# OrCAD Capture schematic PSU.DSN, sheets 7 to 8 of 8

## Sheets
7 FPGA: size A3; title: CONTINUOUS POWER SUPPLY ADC ACQUISITION MODE; note: POF_TMR
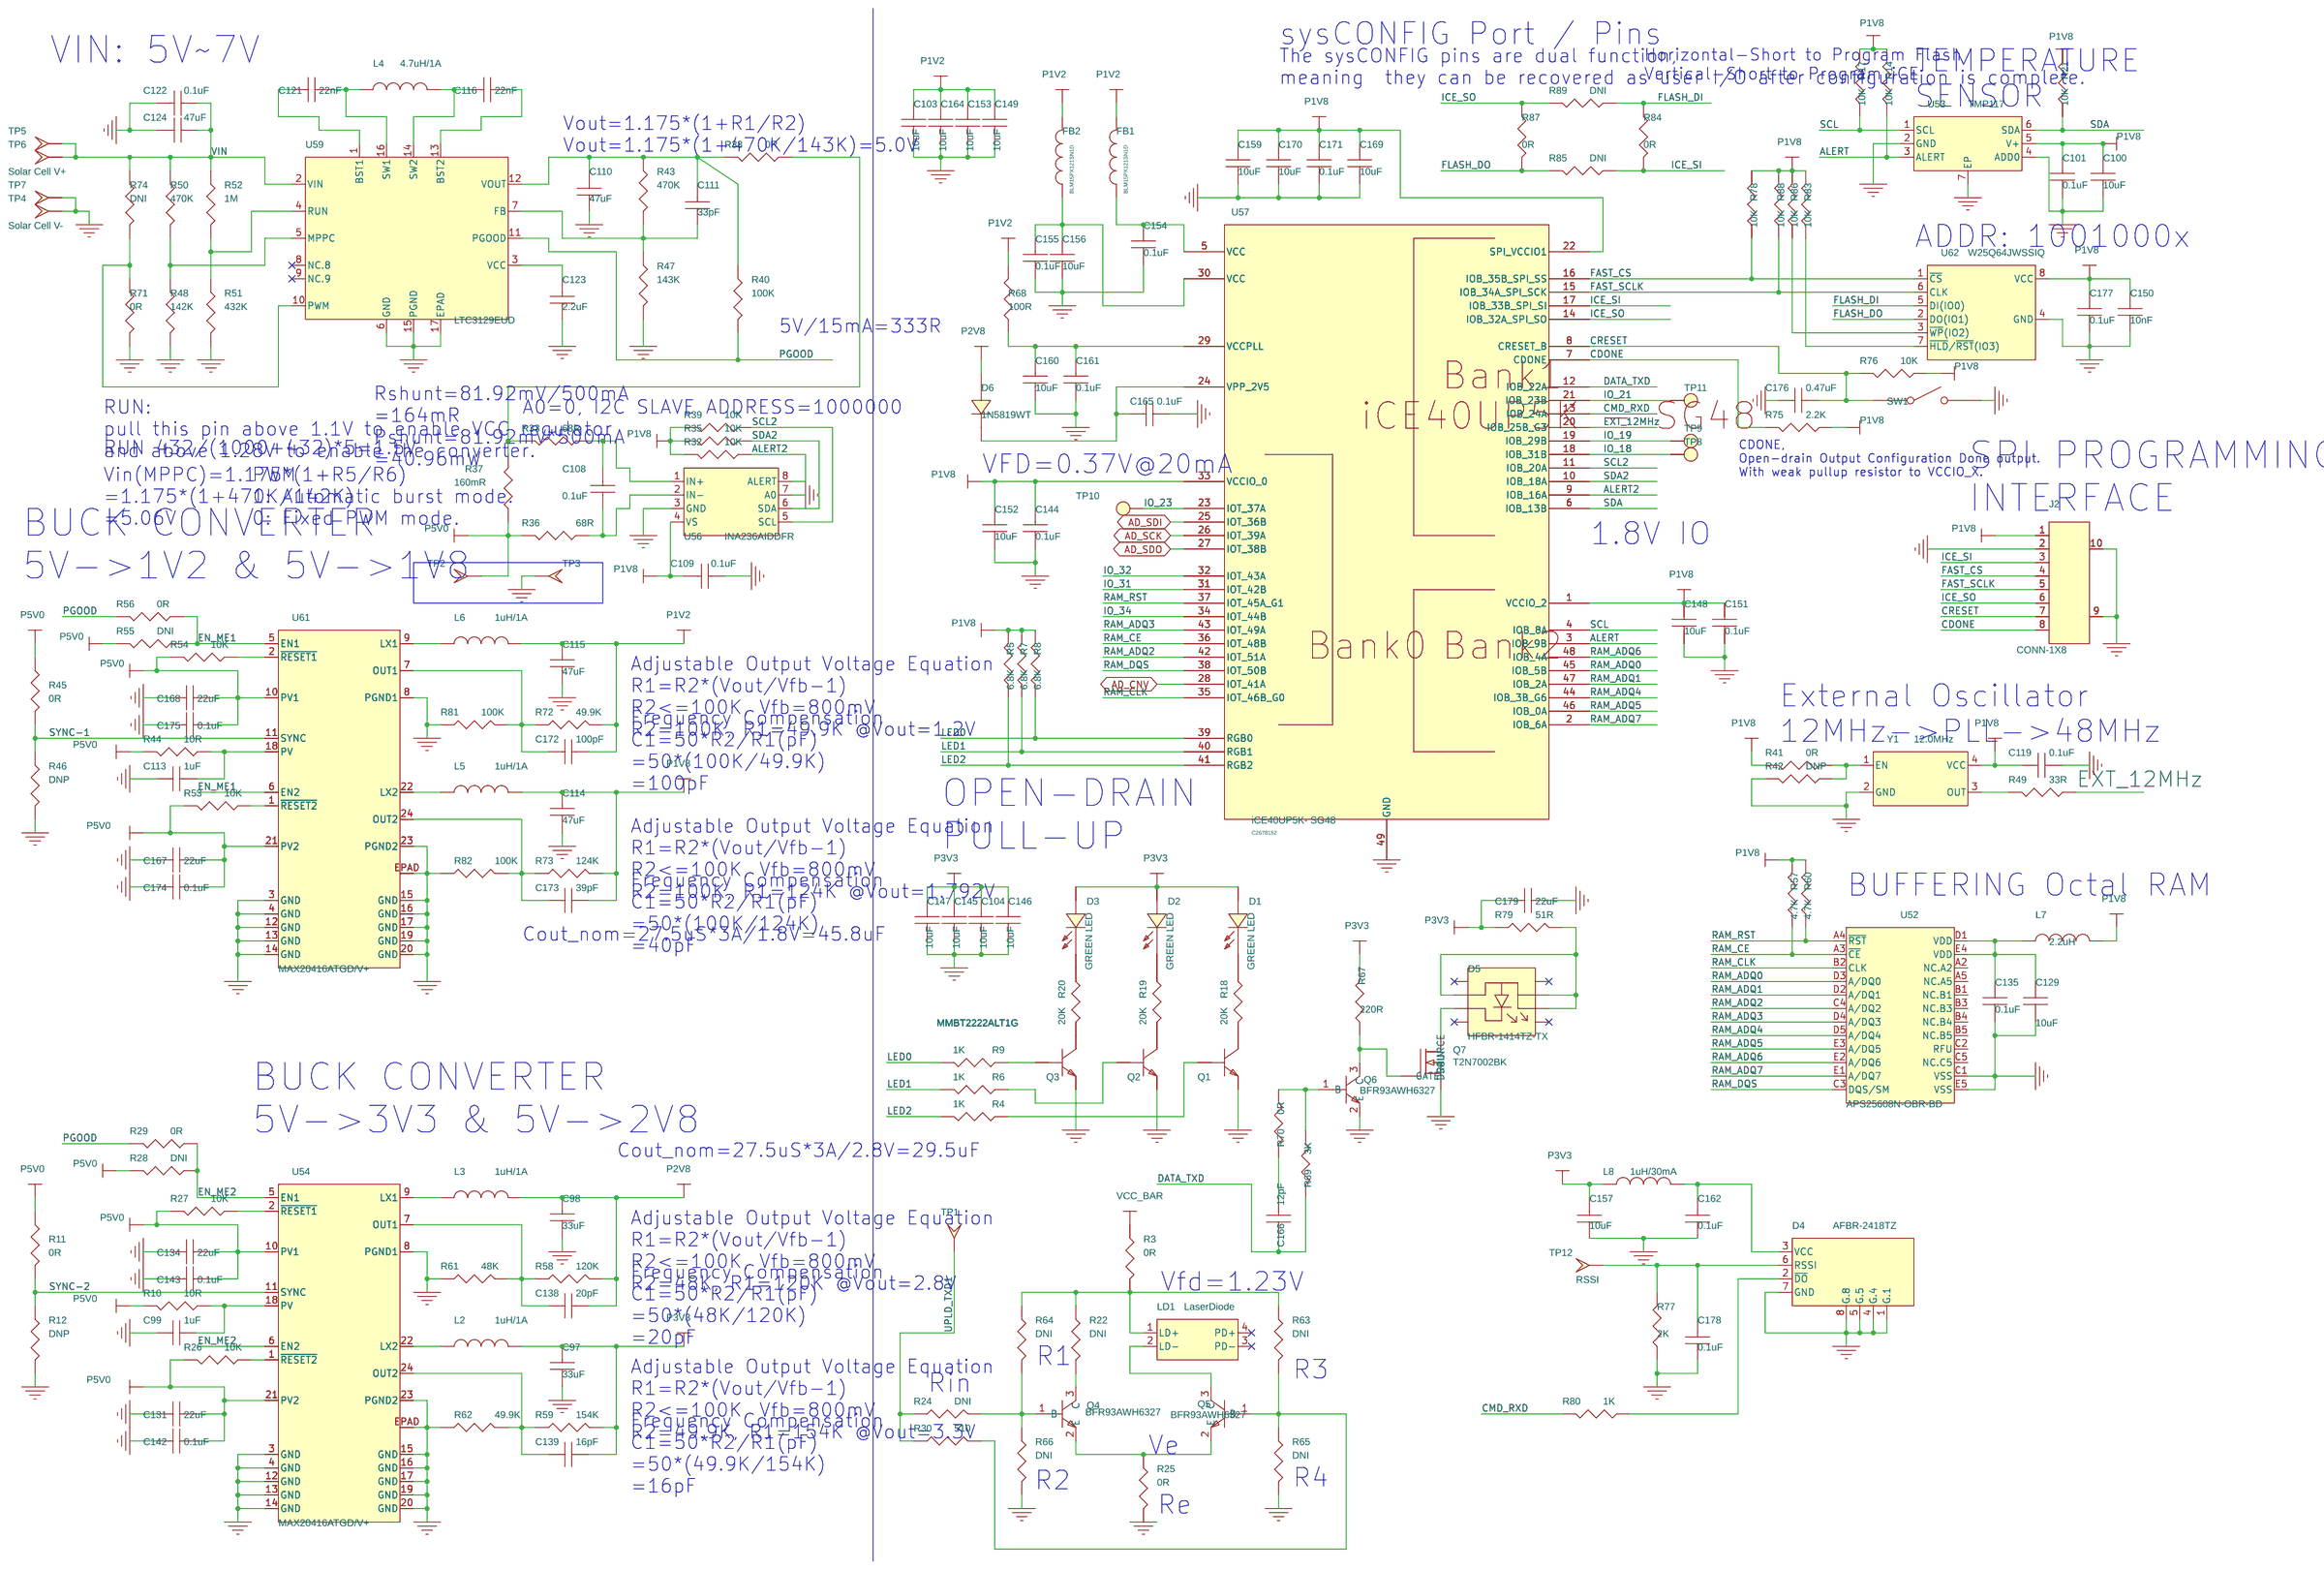
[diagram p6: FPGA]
8 BLOCK: title: PART ONE - POWER SUPPLY UNIT BLOCK DIAGRAM; note: PoF TINY DUAL CAMERA PROJECT
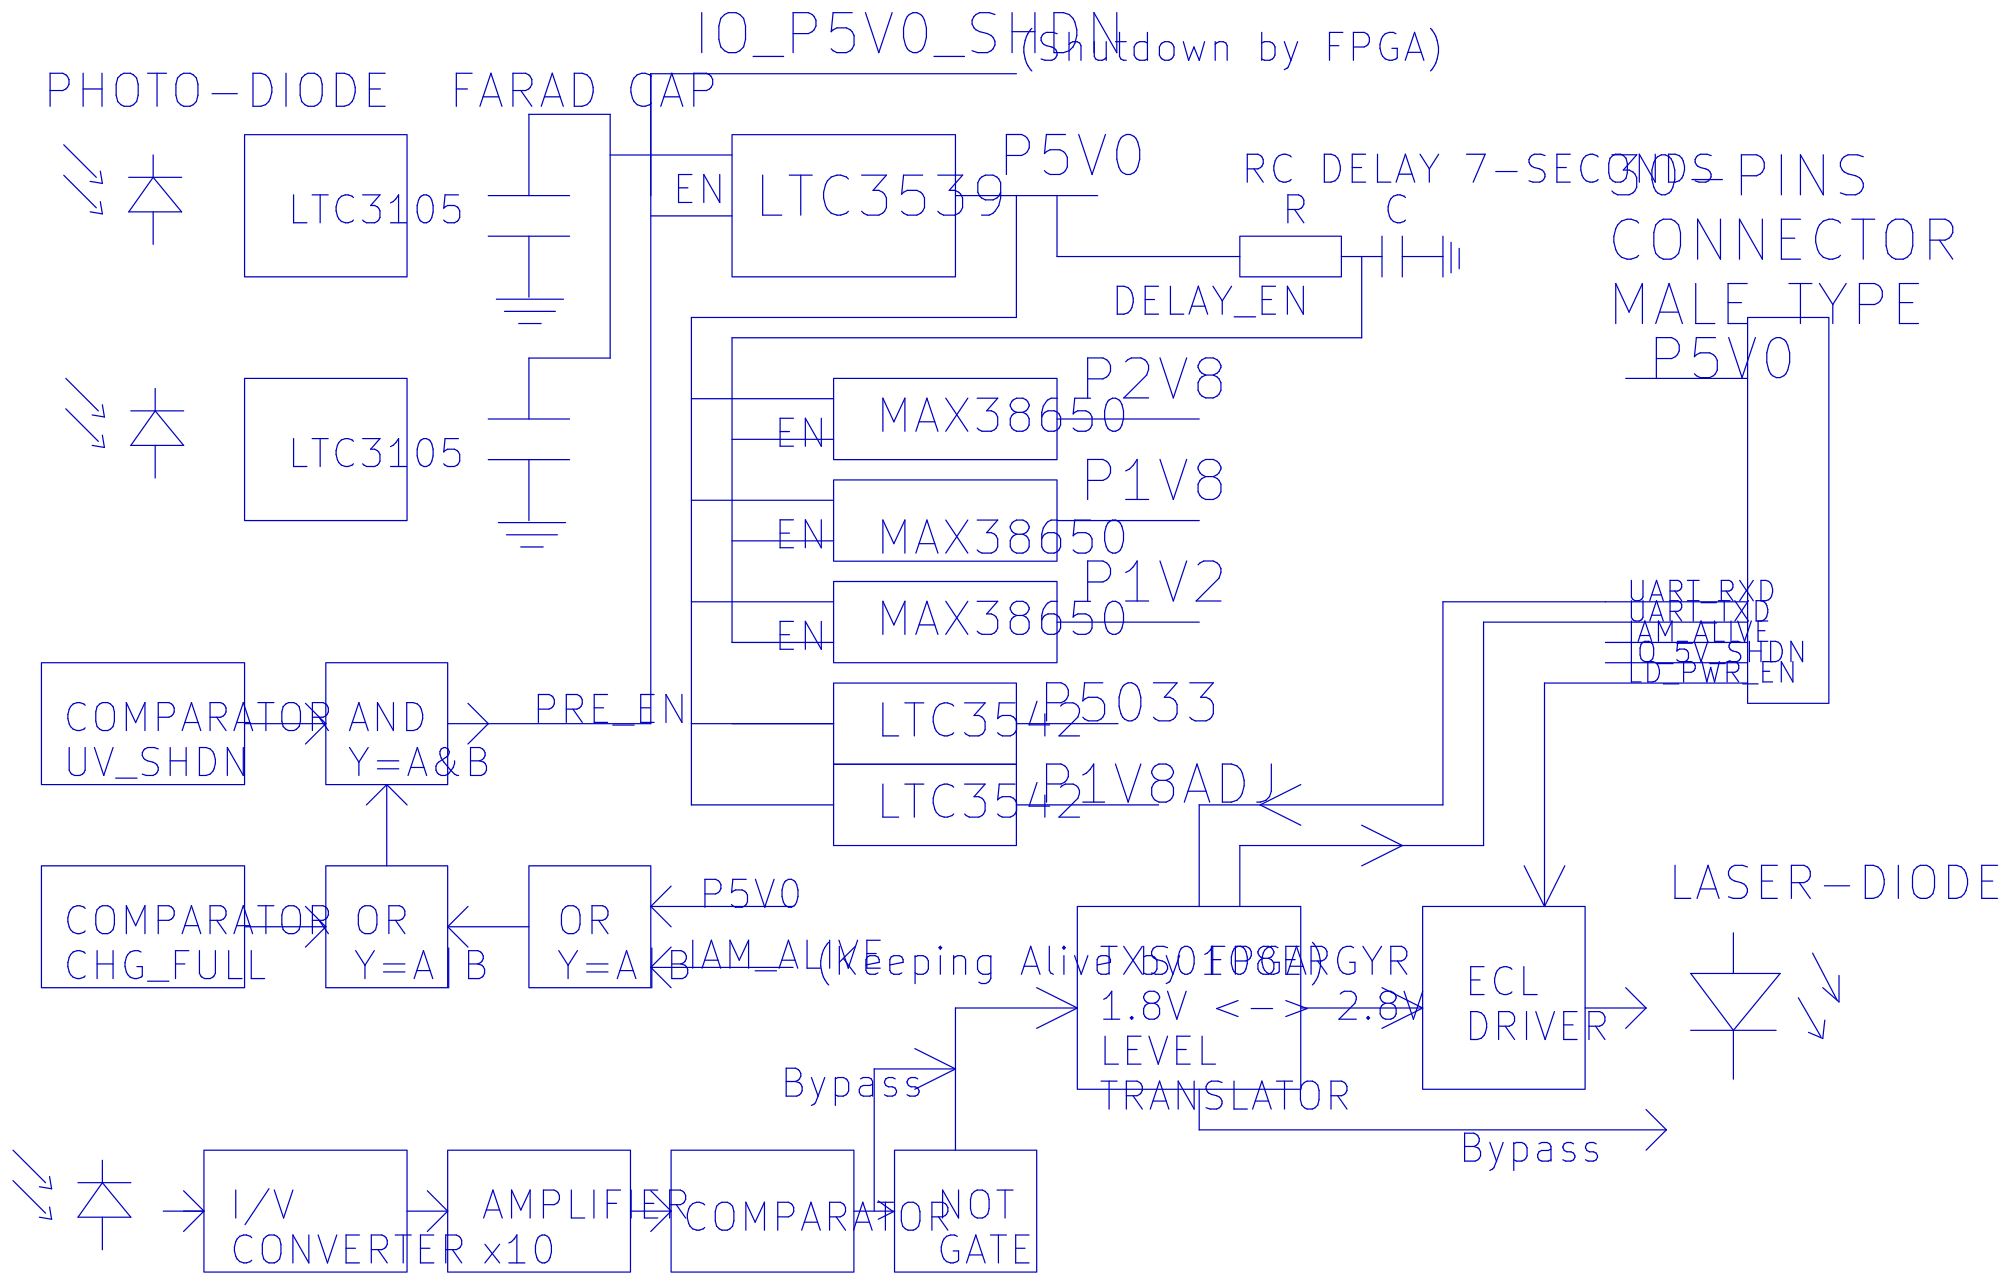
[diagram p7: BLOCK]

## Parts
C97  33uF  [C1206_SMT]
C98  33uF  [C1206_SMT]
C99  1uF  [C0402_SMT]
C100  10uF  [C0402_SMT]
C101  0.1uF  [C0402_SMT]
C103  10uF  [C0402_SMT]
C104  10uF  [C0402_SMT]
C108  0.1uF  [C0402_SMT]
C109  0.1uF  [C0402_SMT]
C110  47uF  [C1206_SMT]
C111  33pF  [C0402_SMT]
C113  1uF  [C0402_SMT]
C114  47uF  [C1206_SMT]
C115  47uF  [C1206_SMT]
C116  22nF  [C0402_SMT]
C119  0.1uF  [C0402_SMT]
C121  22nF  [C0402_SMT]
C122  0.1uF  [C0402_SMT]
C123  2.2uF  [C0402_SMT]
C124  47uF  [C1206_SMT]
C129  10uF  [C0603_SMT]
C131  22uF  [C0603_SMT]
C134  22uF  [C0603_SMT]
C135  0.1uF  [C0402_SMT]
C138  20pF  [C0402_SMT]
C139  16pF  [C0402_SMT]
C142  0.1uF  [C0402_SMT]
C143  0.1uF  [C0402_SMT]
C144  0.1uF  [C0402_SMT]
C145  10uF  [C0402_SMT]
C146  10uF  [C0402_SMT]
C147  10uF  [C0402_SMT]
C148  10uF  [C0402_SMT]
C149  10uF  [C0402_SMT]
C150  10nF  [C0402_SMT]
C151  0.1uF  [C0402_SMT]
C152  10uF  [C0402_SMT]
C153  10uF  [C0402_SMT]
C154  0.1uF  [C0402_SMT]
C155  0.1uF  [C0402_SMT]
C156  10uF  [C0402_SMT]
C157  10uF  [C0402_SMT]
C159  10uF  [C0402_SMT]
C160  10uF  [C0402_SMT]
C161  0.1uF  [C0402_SMT]
C162  0.1uF  [C0402_SMT]
C164  10uF  [C0402_SMT]
C165  0.1uF  [C0402_SMT]
C166  12pF  [C0402_SMT]
C167  22uF  [C0603_SMT]
C168  22uF  [C0603_SMT]
C169  10uF  [C0402_SMT]
C170  10uF  [C0402_SMT]
C171  0.1uF  [C0402_SMT]
C172  100pF  [C0402_SMT]
C173  39pF  [C0402_SMT]
C174  0.1uF  [C0402_SMT]
C175  0.1uF  [C0402_SMT]
C176  0.47uF  [C0402_SMT]
C177  0.1uF  [C0402_SMT]
C178  0.1uF  [C0402_SMT]
C179  22uF  [C0603_SMT]
D1  GREEN LED  [LED0402_SMT]
D2  GREEN LED  [LED0402_SMT]
D3  GREEN LED  [LED0402_SMT]
D4  AFBR-2418TZ  [AFBR-2418TZ]
D5  HFBR-1414TZ-TX  [HFBR-1414TZ-TX]
D6  1N5819WT  [SOD-523]
FB1  BLM15PX121SN1D  [L0402_SMT]
FB2  BLM15PX121SN1D  [L0402_SMT]
J2  CONN-1X8  [FPC-0D5-8P]
L2  1uH/1A  [L1210]
L3  1uH/1A  [L1210]
L4  4.7uH/1A  [IND_SMD_4D4X4D2]
L5  1uH/1A  [L1210]
L6  1uH/1A  [L1210]
L7  2.2uH  [L0402]
L8  1uH/30mA  [L0402_SMT]
LD1  LaserDiode  [LD_CIR_THR_4P]
Q1  MMBT2222ALT1G  [SOT-23-3]
Q2  MMBT2222ALT1G  [SOT-23-3]
Q3  MMBT2222ALT1G  [SOT-23-3]
Q4  BFR93AWH6327  [SOT23-3]
Q5  BFR93AWH6327  [SOT23-3]
Q6  BFR93AWH6327  [SOT23-3]
Q7  T2N7002BK  [SOT23-3]
R3  0R  [R0402_SMT]
R4  1K  [R0402_SMT]
R5  6.8K  [R0402_SMT]
R6  1K  [R0402_SMT]
R7  6.8K  [R0402_SMT]
R8  6.8K  [R0402_SMT]
R9  1K  [R0402_SMT]
R10  10R  [R0402_SMT]
R11  0R  [R0402_SMT]
R12  DNP  [R0402_SMT]
R14  10K  [R0402_SMT]
R17  10K  [R0402_SMT]
R18  20K  [R0402_SMT]
R19  20K  [R0402_SMT]
R20  20K  [R0402_SMT]
R21  10K  [R0402_SMT]
R22  DNI  [R0402_SMT]
R24  DNI  [R0402_SMT]
R25  0R  [R0402_SMT]
R26  10K  [R0402_SMT]
R27  10K  [R0402_SMT]
R28  DNI  [R0402_SMT]
R29  0R  [R0402_SMT]
R30  510  [R0402_SMT]
R32  10K  [R0402_SMT]
R33  68R  [R0402_SMT]
R35  10K  [R0402_SMT]
R36  68R  [R0402_SMT]
R37  160mR  [R0805_SMT]
R38  0R  [R0402_SMT]
R39  10K  [R0402_SMT]
R40  100K  [R0402_SMT]
R41  0R  [R0402_SMT]
R42  DNP  [R0402_SMT]
R43  470K  [R0402_SMT]
R44  10R  [R0402_SMT]
R45  0R  [R0402_SMT]
R46  DNP  [R0402_SMT]
R47  143K  [R0402_SMT]
R48  142K  [R0402_SMT]
R49  33R  [R0402_SMT]
R50  470K  [R0402_SMT]
R51  432K  [R0402_SMT]
R52  1M  [R0402_SMT]
R53  10K  [R0402_SMT]
R54  10K  [R0402_SMT]
R55  DNI  [R0402_SMT]
R56  0R  [R0402_SMT]
R57  4.7K  [R0402_SMT]
R58  120K  [R0402_SMT]
R59  154K  [R0402_SMT]
R60  4.7K  [R0402_SMT]
R61  48K  [R0402_SMT]
R62  49.9K  [R0402_SMT]
R63  DNI  [R0402_SMT]
R64  DNI  [R0402_SMT]
R65  DNI  [R0402_SMT]
R66  DNI  [R0402_SMT]
R67  220R  [R0402_SMT]
R68  100R  [R0402_SMT]
R69  3K  [R0402_SMT]
R70  0R  [R0402_SMT]
R71  0R  [R0402_SMT]
R72  49.9K  [R0402_SMT]
R73  124K  [R0402_SMT]
R74  DNI  [R0402_SMT]
R75  2.2K  [R0402_SMT]
R76  10K  [R0402_SMT]
R77  2K  [R0402_SMT]
R78  10K  [R0402_SMT]
R79  51R  [R0402_SMT]
R80  1K  [R0402_SMT]
R81  100K  [R0402_SMT]
R82  100K  [R0402_SMT]
R83  10K  [R0402_SMT]
R84  0R  [R0402_SMT]
R85  DNI  [R0402_SMT]
R86  10K  [R0402_SMT]
R87  0R  [R0402_SMT]
R88  10K  [R0402_SMT]
R89  DNI  [R0402_SMT]
SW1  SW KEY-SPST  [SW_SMD_2P_L3D9_W3D0_P4D5]
TP1  1  [TP_THR_1D0_1D5]
TP2  Solar Cell V+  [TP_THR_REC_1D5_3D5]
TP3  Solar Cell V+  [TP_THR_REC_1D5_3D5]
TP4  Solar Cell V-  [TP_THR_1D8_1D2]
TP5  Solar Cell V+  [TP_THR_1D8_1D2]
TP6  Solar Cell V+  [TP_THR_1D8_1D2]
TP7  Solar Cell V-  [TP_THR_1D8_1D2]
TP8  T POINT R  [TP_SMD_1D0_NP]
TP9  T POINT R  [TP_SMD_1D0_NP]
TP10  T POINT R  [TP_SMD_1D0_NP]
TP11  T POINT R  [TP_SMD_1D0_NP]
TP12  RSSI  [TP_THR_1D8_1D2]
U52  APS25608N-OBR-BD  [BGA-24]
U53  TMP117  [WDFN-6-EP-2x2]
U54  MAX20416ATGD/V+  [TQFN-24]
U56  INA236AIDDFR  [SOT-23-8]
U57  iCE40UP5K- SG48  [QFN-48]
U59  LTC3129EUD  [QFN-16-3x3]
U61  MAX20416ATGD/V+  [TQFN-24]
U62  W25Q64JWSSIQ  [SOIC-8]
Y1  12.0MHz  [SMD2520-4P]

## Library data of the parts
C97 C98 C110 C114 C115 C124 = CAP_NP: Memo: TDK MLCC 10V CGA5L1X7S1A226MT0Y0N; SIGNAL_MODEL: DEFAULT_CAPACITOR_2.2e+07pF_2_1
C99 C111 C113 C116 C121 C123 C131 C134 C142 C143 C157 C162 C167 C168 C174 C175 C178 C179 = CAP_NP: Memo: MLCC 10V - Kyocera AVXF951A106MPAAQ2; SIGNAL_MODEL: DEFAULT_CAPACITOR_1e+07pF_2_1
C100 C101 = CAP_NP
C103 C104 C145-C149 C152 C153 C156 C159 C160 C164 C169 C170 = CAP_NP: JLC: C15195
C108 C109 C122 = CAP_NP: JLC: C327064; SIGNAL_MODEL: DEFAULT_CAPACITOR_33.000000pF_2_1
C119 C138 C139 C166 C172 C173 = CAP_NP: JLC: C307331; Memo: MLCC 10V - Kyocera AVXF951A106MPAAQ2; SIGNAL_MODEL: DEFAULT_CAPACITOR_1e+07pF_2_1
C129 = CAP_NP: JLC: C96446
C135 C144 C151 C154 C161 C165 C176 C177 = CAP_NP: JLC: C307331
C150 C155 C171 = CAP_NP: JLC: C14445
D1-D3 = LED: JLC: C130723
D4 = AFBR-2418TZ
D5 = HFBR-1414TZ-TX
D6 = DIODE: JLC: C83482
FB1 FB2 = INDUCTOR: JLC: C14709
J2 = CONN-1X8
L2-L7 = INDUCTOR: JLC: C167208; Memo: 4.7uH 1A - TDK VLS3015ET-4R7M 3.0mm(L)*3.0mm(W)*1.5mm(H); SIGNAL_MODEL: DEFAULT_INDUCTOR_4700nH_2_1
L8 = INDUCTOR
LD1 = LaserDiode_0: Memo: Laser Diode
Q1-Q3 = MMBT2222AL: JLC: C82460
Q4-Q6 = 2SC1815: JLC: C727146; Memo: NPN TRANSISTOR
Q7 = MOSFET_N_0
R3 R22 R25 R67 R77 R79 R80 = R: SIGNAL_MODEL: DEFAULT_RESISTOR_40.000000OHM_2_1
R4 R6 R9 R69 R70 R76 R78 R83-R89 = R: JLC: C60490
R5 R7 R8 R14 R17-R21 = R: JLC: C2930116
R10-R12 R26-R29 R38 R40-R56 R58 R59 R61 R62 R71-R74 R81 R82 = R: JLC: C106231; SIGNAL_MODEL: DEFAULT_RESISTOR_10000OHM_2_1
R24 R30 R63-R66 = R: SIGNAL_MODEL: DEFAULT_RESISTOR_510.000000OHM_2_1
R32 R33 R35-R37 R39 = R
R57 R60 = R: JLC: C105871
R68 = R: JLC: C106232
R75 = R: JLC: C114762
SW1 = SW_KEY-SPST: JLC: C720477
TP1-TP7 TP12 = T_POINT_A: Memo: SMD Test Point Outer Diameter 2.0mm
TP8-TP11 = T_POINT_R
U52 = APS25608N-OBR-BD_2: JLC: Mouser
U53 = TMP117
U54 U61 = MAX20416ATGD_V+
U56 = INA236AIDDFR_v2
U57 = iCE40UP5K-_SG48: JLC: C2678152
U59 = LTC3129EUD
U62 = W25Q64JW: JLC: C2985658
Y1 = OSCILLATOR

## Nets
GND: C97.2 C98.2 C99.1 C100.2 C101.2 C103.2 C104.2 C109.1 C110.1 C113.1 C114.2 C115.2 C119.2 C122.2 C123.1 C124.2 C129.2 C131.1 C134.1 C135.2 C142.1 C143.1 C144.2 C145.2 C146.2 C147.2 C148.2 C149.2 C150.2 C151.2 C152.2 C153.2 C154.2 C155.2 C156.2 C157.1 C159.2 C160.2 C161.2 C162.1 C164.2 C165.2 C167.1 C168.1 C169.2 C170.2 C171.2 C174.1 C175.1 C176.1 C177.2 C178.1 C179.2 D4.1(G.1) D4.4(G.4) D4.5(G.5) D4.7(GND) D4.8(G.8) J2.2 J2.9 J2.10 Q1.2(EMITTER) Q2.2(EMITTER) Q3.2(EMITTER) Q6.2(E) Q7.2(SOURCE) R12.2 R25.2 R42.2 R46.2 R47.2 R48.2 R51.2 R61.1 R62.1 R65.2 R66.2 R71.2 R77.1 R81.1 R82.1 SW1.2 TP3.1(TP) TP4.1(TP) TP7.1(TP) U52.C1(VSS) U52.E5(VSS) U53.2(GND) U53.4(ADD0) U53.7(EP) U54.3(GND) U54.4(GND) U54.8(PGND1) U54.12(GND) U54.13(GND) U54.14(GND) U54.15(GND) U54.16(GND) U54.17(GND) U54.19(GND) U54.20(GND) U54.23(PGND2) U54.EPAD U56.3(GND) U56.7(A0) U57.49(GND) U59.6(GND) U59.15(PGND) U59.17(EPAD) U61.3(GND) U61.4(GND) U61.8(PGND1) U61.12(GND) U61.13(GND) U61.14(GND) U61.15(GND) U61.16(GND) U61.17(GND) U61.19(GND) U61.20(GND) U61.23(PGND2) U61.EPAD U62.4(GND) Y1.2(GND) ; also on sheet 2 6
P1V2: C103.1 C115.1 C149.1 C153.1 C164.1 C172.2 FB1.2 FB2.2 L6.2 R68.2 R72.2
P1V8: C100.1 C101.1 C109.2 C114.1 C119.1 C144.1 C148.1 C150.1 C151.1 C152.1 C159.1 C169.1 C170.1 C171.1 C173.2 C177.1 J2.1 L5.2 L7.2 R5.2 R7.2 R8.2 R14.2 R17.2 R21.2 R32.2 R35.2 R39.2 R41.2 R57.2 R60.2 R73.2 R75.1 R76.1 R78.2 R83.2 R86.2 R88.2 U53.5(V+) U56.4(VS) U57.1(VCCIO_2) U57.22(SPI_VCCIO1) U57.33(VCCIO_0) U62.8(VCC) Y1.4(VCC) ; also on sheet 2 6
P2V8: C98.1 C138.2 D6.2(A) L3.2 R58.2
P3V3: C97.1 C104.1 C139.2 C145.1 C146.1 C147.1 C157.2 C179.1 D1.2(ANODE) D2.2(ANODE) D3.2(ANODE) L2.2 L8.1 R3.1 R59.2 R67.2 R79.1 ; also on sheet 6
P5V0: C131.2 C134.2 C142.2 C143.2 C167.2 C168.2 C174.2 C175.2 R10.2 R11.1 R26.2 R27.2 R28.2 R36.2 R37.2 R44.2 R45.1 R53.2 R54.2 R55.2 TP2.1(TP) U54.10(PV1) U54.21(PV2) U61.10(PV1) U61.21(PV2)
VIN: C122.1 C124.1 R50.1 R52.1 R74.1 TP5.1(TP) TP6.1(TP) U59.2(VIN)
AD_CNV: U57.28(IOT_41A) ; also on sheet 6
AD_SCK: U57.26(IOT_39A) ; also on sheet 6
AD_SDI: U57.25(IOT_36B) ; also on sheet 6
AD_SDO: U57.27(IOT_38B) ; also on sheet 6
ALERT: R14.1 U53.3(ALERT) U57.3(IOB_9B)
ALERT2: R32.1 U56.8(ALERT) U57.9(IOB_16A)
CDONE: J2.8 R75.2 U57.7(CDONE)
CMD_RXD: R80.2 U57.13(IOB_24A)
CRESET: C176.2 J2.7 R76.2 SW1.1 U57.8(CRESET_B)
DATA_TXD: C166.1 R69.1 U57.12(IOB_22A)
EN_ME1: R55.1 R56.1 U61.5(EN1) U61.6(EN2)
EN_ME2: R28.1 R29.1 U54.5(EN1) U54.6(EN2)
EXT_12MHz (page FPGA): R49.1 U57.20(IOB_25B_G3)
FAST_CS: J2.4 R78.1 U57.16(IOB_35B_SPI_SS) U62.1(~{CS})
FAST_SCLK: J2.5 R88.1 U57.15(IOB_34A_SPI_SCK) U62.6(CLK)
FLASH_DI: R84.1 R89.1 U62.5(DI(IO0))
FLASH_DO: R85.2 R87.2 U62.2(DO(IO1))
ICE_SI: J2.3 R84.2 R85.1 U57.17(IOB_33B_SPI_SI)
ICE_SO: J2.6 R87.1 R89.2 U57.14(IOB_32A_SPI_SO)
IO_18: TP8.1(TP) U57.18(IOB_31B)
IO_19: TP9.1(TP) U57.19(IOB_29B)
IO_21: TP11.1(TP) U57.21(IOB_23B)
IO_23: TP10.1(TP) U57.23(IOT_37A)
IO_31: U57.31(IOT_42B)
IO_32: U57.32(IOT_43A)
IO_34: U57.34(IOT_44B)
LED0: R8.1 R9.1 U57.39(RGB0)
LED1: R6.1 R7.1 U57.40(RGB1)
LED2: R4.1 R5.1 U57.41(RGB2)
NC.A2: U52.A2(NC.A2)
NC.A5: U52.A5(NC.A5)
NC.B1: U52.B1(NC.B1)
NC.B3: U52.B3(NC.B3)
NC.B4: U52.B4(NC.B4)
NC.B5: U52.B5(NC.B5)
NC.C5: U52.C5(NC.C5)
PGOOD: R29.2 R40.2 R56.2 U59.11(PGOOD)
RAM_ADQ0: U52.D3(A/DQ0) U57.45(IOB_5B)
RAM_ADQ1: U52.D2(A/DQ1) U57.47(IOB_2A)
RAM_ADQ2: U52.C4(A/DQ2) U57.42(IOT_51A)
RAM_ADQ3: U52.D4(A/DQ3) U57.43(IOT_49A)
RAM_ADQ4: U52.D5(A/DQ4) U57.44(IOB_3B_G6)
RAM_ADQ5: U52.E3(A/DQ5) U57.46(IOB_0A)
RAM_ADQ6: U52.E2(A/DQ6) U57.48(IOB_4A)
RAM_ADQ7: U52.E1(A/DQ7) U57.2(IOB_6A)
RAM_CE: R57.1 U52.A3(~{CE}) U57.36(IOT_48B)
RAM_CLK: U52.B2(CLK) U57.35(IOT_46B_G0)
RAM_DQS: U52.C3(DQS/SM) U57.38(IOT_50B)
RAM_RST: R60.1 U52.A4(~{RST}) U57.37(IOT_45A_G1)
RFU: U52.C2(RFU)
SCL: R17.1 U53.1(SCL) U57.4(IOB_8A)
SCL2: R39.1 U56.5(SCL) U57.11(IOB_20A)
SDA: R21.1 U53.6(SDA) U57.6(IOB_13B)
SDA2: R35.1 U56.6(SDA) U57.10(IOB_18A)
SYNC-1 (page FPGA): R45.2 R46.1 U61.11(SYNC)
SYNC-2 (page FPGA): R11.2 R12.1 U54.11(SYNC)
UPLD_TXD1: R24.1 R30.1 TP1.1(TP)
N1648364: C155.1 C156.1 FB2.1 U57.30(VCC)
N1648368: C154.1 FB1.1 U57.5(VCC)
N1648564: R86.1 U62.3(~{WP}(IO2))
N1648568: R83.1 U62.7(~{HLD}/~{RST}(IO3))
N1648824: C160.1 C161.1 R68.1 U57.29(VCCPLL)
N1648996: C165.1 D6.1(K) U57.24(VPP_2V5)
N1650132: C129.1 C135.1 L7.1 U52.D1(VDD) U52.E4(VDD)
N1650410: Q1.1(BASE) R4.2
N1650418: Q2.1(BASE) R6.2
N1650426: Q3.1(BASE) R9.2
N3114235: L6.1 U61.9(LX1)
N3114271: R54.1 U61.2(~{RESET1})
N3114319: C172.1 R72.1 R81.2 U61.7(OUT1)
N3114529: C113.2 R44.1 U61.18(PV)
N3114639: L5.1 U61.22(LX2)
N3114667: R53.1 U61.1(~{RESET2})
N3114699: C173.1 R73.1 R82.2 U61.24(OUT2)
N3116255: L3.1 U54.9(LX1)
N3116291: R27.1 U54.2(~{RESET1})
N3116339: C138.1 R58.1 R61.2 U54.7(OUT1)
N3116549: C99.2 R10.1 U54.18(PV)
N3116659: L2.1 U54.22(LX2)
N3116687: R26.1 U54.1(~{RESET2})
N3116719: C139.1 R59.1 R62.2 U54.24(OUT2)
N3119450: C116.1 L4.2 U59.14(SW2)
N3119456: C121.2 L4.1 U59.16(SW1)
N3119520: C121.1 U59.1(BST1)
N3119553: C116.2 U59.13(BST2)
N3119651: R51.1 R52.2 U59.4(RUN)
N3122265: R71.1 R74.2 U59.10(PWM)
N3122703: C123.2 U59.3(VCC)
N3123371: C110.2 C111.2 R38.2 R40.1 R43.1 U59.12(VOUT)
N3124274: C111.1 R43.2 R47.1 U59.7(FB)
N3124471: R33.2 R37.1 R38.1
N3127570: R48.1 R50.2 U59.5(MPPC)
N3144574: LD1.1(LD+) R3.2 R22.1 R63.1 R64.1
N3144674: LD1.2(LD-) Q5.3(C)
N3144682: Q4.1(B) R24.2 R64.2 R66.1
N3144686: Q4.3(C) R22.2
N3144698: Q5.1(B) R30.2 R63.2 R65.1
N3144846: Q4.2(E) Q5.2(E) R25.1
N3153529: D5.2 D5.6 D5.7 R79.2
N3153778: D5.3 Q7.3(DRAIN)
N3452855: R41.1 R42.1 Y1.1(EN)
N3452915: R49.2 Y1.3(OUT)
N3466785: Q6.3(C) Q7.1(GATE) R67.1
N3564575: C162.2 D4.3(VCC) L8.2
N3565945: C178.2 D4.6(RSSI) R77.2 TP12.1(TP)
N3566834: D4.2(~{DO}) R80.1
N3567309: C166.2 R70.1
N3567360: Q6.1(B) R69.2 R70.2
N3576651: C108.2 R33.1 U56.1(IN+)
N3576675: C108.1 R36.1 U56.2(IN-)
N3724313: D1.1(CATHODE) R18.2
N3724314: Q2.3(COLLECTOR) R19.1
N3724318: Q1.3(COLLECTOR) R18.1
N3724319: Q3.3(COLLECTOR) R20.1
N3724327: D3.1(CATHODE) R20.2
N3724329: D2.1(CATHODE) R19.2

Not connected (* = marked no-connect by the designer): D5 1* 4* 5* 8*; LD1 3(PD-)* 4(PD+)*; U59 8(NC.8)* 9(NC.9)*

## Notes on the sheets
sheet 7
- sysCONFIG Port / Pins
- VIN: 5V~7V
- The sysCONFIG pins are dual function,
  meaning  they can be recovered as user I/O after configuration is complete.
- Horizontal-Short to Program Flash
  Vertical-Short to Program iCE
- TEMPERATURE
  SENSOR
- Vout=1.175*(1+R1/R2)
  Vout=1.175*(1+470K/143K)=5.0V
- ADDR: 1001000x
- 5V/15mA=333R
- Rshunt=81.92mV/500mA
  =164mR
  Pshunt=81.92mV*500mA
  =40.96mW
- RUN:
  pull this pin above 1.1V to enable VCC regulator
  and above 1.28V to enable the converter.
- A0=0, I2C SLAVE ADDRESS=1000000
- RUN 432/(1000+432)*5=1.5V
- CDONE,
  Open-drain Output Configuration Done output.
  With weak pullup resistor to VCCIO_X.
- SPI PROGRAMMING
  INTERFACE
- VFD=0.37V@20mA
- Vin(MPPC)=1.175*(1+R5/R6)
  =1.175*(1+470K/142K)
  =5.06V
- PWM
  1: Automatic burst mode.
  0: Fixed PWM mode.
- BUCK CONVERTER
  5V->1V2 & 5V->1V8
- 1.8V IO
- Adjustable Output Voltage Equation
  R1=R2*(Vout/Vfb-1)
  R2<=100K, Vfb=800mV
  R2=100K, R1=49.9K @Vout=1.2V
- External Oscillator
  12MHz->PLL->48MHz
- Frequency Compensation
  C1=50*R2/R1(pF)
  =50*(100K/49.9K)
  =100pF
- OPEN-DRAIN
  PULL-UP
- Adjustable Output Voltage Equation
  R1=R2*(Vout/Vfb-1)
  R2<=100K, Vfb=800mV
  R2=100K, R1=124K @Vout=1.792V
- Frequency Compensation
  C1=50*R2/R1(pF)
  =50*(100K/124K)
  =40pF
- BUFFERING Octal RAM
- Cout_nom=27.5uS*3A/1.8V=45.8uF
- BUCK CONVERTER
  5V->3V3 & 5V->2V8
- Cout_nom=27.5uS*3A/2.8V=29.5uF
- Adjustable Output Voltage Equation
  R1=R2*(Vout/Vfb-1)
  R2<=100K, Vfb=800mV
  R2=48K, R1=120K @Vout=2.8V
- Frequency Compensation
  C1=50*R2/R1(pF)
  =50*(48K/120K)
  =20pF
- Vfd=1.23V
- R1
- Adjustable Output Voltage Equation
  R1=R2*(Vout/Vfb-1)
  R2<=100K, Vfb=800mV
  R2=49.9K, R1=154K @Vout=3.3V
- R3
- Rin
- Frequency Compensation
  C1=50*R2/R1(pF)
  =50*(49.9K/154K)
  =16pF
- Ve
- R2
- R4
- Re
sheet 8
- IO_P5V0_SHDN
- (Shutdown by FPGA)
- PHOTO-DIODE
- FARAD CAP
- P5V0
- RC DELAY 7-SECONDS
- 30-PINS
  CONNECTOR
  MALE TYPE
- EN
- LTC3539
- LTC3105
- R
- C
- DELAY_EN
- P2V8
- P5V0
- MAX38650
- EN
- LTC3105
- P1V8
- EN
- MAX38650
- P1V2
- UART_RXD
- EN
- MAX38650
- IAM_ALIVE
- UART_TXD
- IO_5V_SHDN
- LD_PWR_EN
- P5033
- COMPARATOR
  UV_SHDN
- AND
  Y=A&B
- PRE_EN
- LTC3542
- P1V8ADJ
- LTC3542
- P5V0
- LASER-DIODE
- COMPARATOR
  CHG_FULL
- OR
  Y=A|B
- OR
  Y=A|B
- IAM_ALIVE
- (Keeping Alive by FPGA)
- TXS0108ERGYR
  1.8V <-> 2.8V
  LEVEL
  TRANSLATOR
- ECL
  DRIVER
- Bypass
- Bypass
- I/V
  CONVERTER
- AMPLIFIER
  x10
- NOT
  GATE
- COMPARATOR
